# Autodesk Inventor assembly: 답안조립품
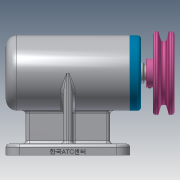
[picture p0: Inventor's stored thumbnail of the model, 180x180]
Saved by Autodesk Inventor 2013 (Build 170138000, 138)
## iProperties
Created: 2020-10
Part Number: 답안조립품
Document SubType Name: Assembly
Designer: 00
Author: 00
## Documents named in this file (12)
- C:\Users\00\Desktop\701004V1030\701004V1030\답안조립품.iam
- C:\Users\00\Desktop\701004V1030\701004V1030\본체.ipt
- C:\Users\00\Desktop\701004V1030\701004V1030\V벨트풀리.ipt
- C:\Users\00\Desktop\701004V1030\701004V1030\멈춤나사 M3.ipt
- C:\Users\00\Desktop\701004V1030\701004V1030\베어링 6004.ipt
- C:\Users\00\Desktop\701004V1030\701004V1030\베어링 51202.ipt
- C:\Users\00\Desktop\701004V1030\701004V1030\볼트 M4.ipt
- C:\Users\00\Desktop\701004V1030\701004V1030\어댑터슬리브.ipt
- C:\Users\00\Desktop\701004V1030\701004V1030\오일 실.ipt
- C:\Users\00\Desktop\701004V1030\701004V1030\축.ipt
- C:\Users\00\Desktop\701004V1030\701004V1030\커버.ipt
- C:\Users\00\Desktop\701004V1030\701004V1030\키 5 x 5 x 16.ipt
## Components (1 placed, 1 different names)
1. V벨트풀리:1 — 플러쉬:1
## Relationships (1: Flush 1)
- 플러쉬:1 [Flush]: V벨트풀리:1
